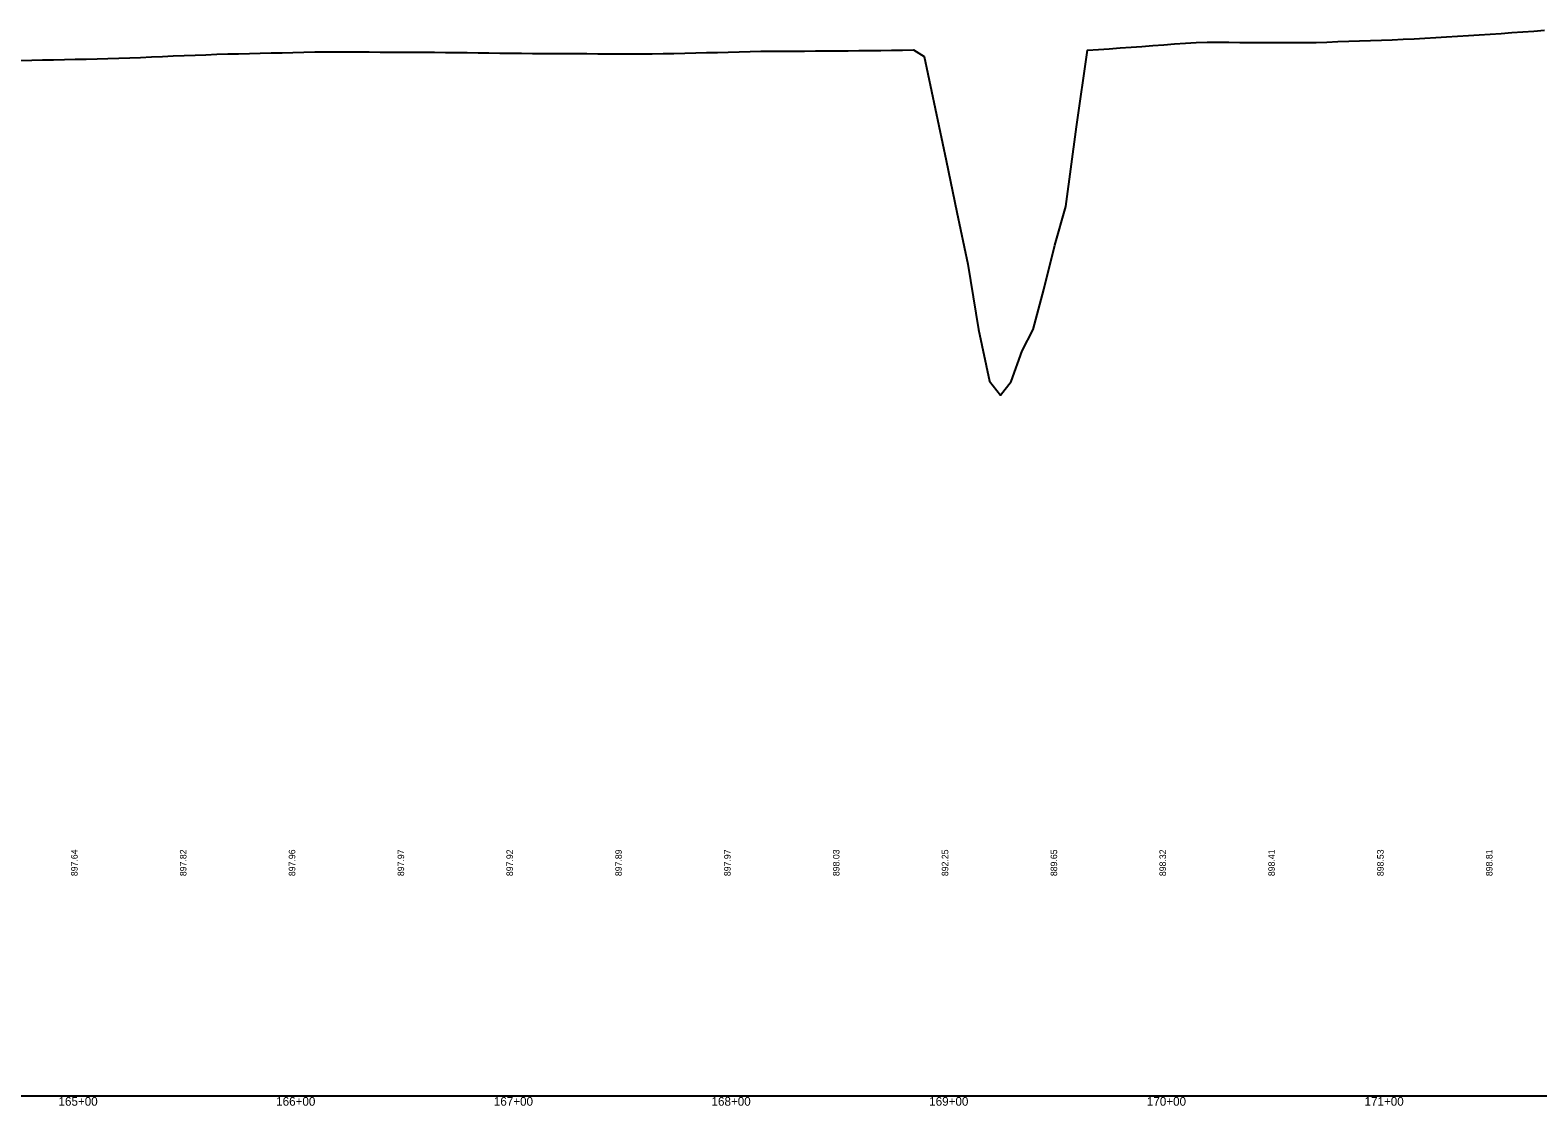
# Model space of a CAD drawing. Extents: x 1475774 to 1484571, y 1098511 to 1113011.
# Drawn here: x 1479549 to 1480241, y 1110507 to 1111001 of the extents above; entities that cross this region are included whole.
import ezdxf

# ---------------------------------------------------------------- set-up
doc = ezdxf.new("R2010")
doc.units = 0
for name, color, linetype in [('RD_DDB_Profile_EX', 7, 'Continuous'), ('RD_DDB_StaTX', 7, 'Continuous'), ('RD_DDB_StripGrade', 7, 'Continuous'), ('RD_GPK_Profile_Cell', 7, 'Continuous')]:
    doc.layers.add(name, color=color, linetype=linetype)

msp = doc.modelspace()

# ---------------------------------------------------------------- linework, layer by layer
at = {"layer": 'RD_DDB_Profile_EX'}
for points in [[(1479964.42, 1110965.08), (1479969.42, 1110941.19), (1479974.42, 1110917.3), (1479979.42, 1110893.42), (1479984.42, 1110863.41), (1479989.42, 1110839.73), (1479994.42, 1110833.29), (1479999.42, 1110839.55), (1480004.42, 1110853.59), (1480009.42, 1110863.52), (1480014.42, 1110881.81), (1480019.42, 1110902.24), (1480024.42, 1110919.92), (1480029.42, 1110956.54), (1480034.42, 1110991.76), (1480039.42, 1110992.13), (1480044.42, 1110992.49), (1480049.42, 1110992.85), (1480054.42, 1110993.21), (1480059.42, 1110993.57), (1480064.42, 1110993.93), (1480069.42, 1110994.29), (1480074.42, 1110994.65), (1480079.42, 1110995.01), (1480084.42, 1110995.37), (1480089.42, 1110995.45), (1480094.42, 1110995.43), (1480099.42, 1110995.42), (1480104.42, 1110995.4), (1480109.42, 1110995.38), (1480114.42, 1110995.37), (1480119.42, 1110995.36), (1480124.42, 1110995.34), (1480129.42, 1110995.32), (1480134.42, 1110995.3), (1480139.42, 1110995.38), (1480144.42, 1110995.56), (1480149.42, 1110995.74), (1480154.42, 1110995.92), (1480159.42, 1110996.1), (1480164.42, 1110996.28), (1480169.42, 1110996.46), (1480174.42, 1110996.63), (1480179.42, 1110996.81), (1480184.42, 1110996.99), (1480189.42, 1110997.26), (1480194.42, 1110997.59), (1480199.42, 1110997.92), (1480204.42, 1110998.25), (1480209.42, 1110998.57), (1480214.42, 1110998.88), (1480219.42, 1110999.21), (1480224.42, 1110999.54), (1480229.42, 1110999.86), (1480234.42, 1111000.19), (1480239.42, 1111000.59), (1480244.42, 1111001.02)], [(1479544.42, 1110987.1), (1479549.42, 1110987.21), (1479554.42, 1110987.32), (1479559.42, 1110987.43), (1479564.42, 1110987.53), (1479569.42, 1110987.63), (1479574.42, 1110987.73), (1479579.42, 1110987.82), (1479584.42, 1110987.91), (1479589.42, 1110988.08), (1479594.42, 1110988.3), (1479599.42, 1110988.52), (1479604.42, 1110988.74), (1479609.42, 1110988.94), (1479614.42, 1110989.14), (1479619.42, 1110989.34), (1479624.42, 1110989.54), (1479629.42, 1110989.73), (1479634.42, 1110989.93), (1479639.42, 1110990.07), (1479644.42, 1110990.19), (1479649.42, 1110990.3), (1479654.42, 1110990.42), (1479659.42, 1110990.53), (1479664.42, 1110990.66), (1479669.42, 1110990.77), (1479674.42, 1110990.89), (1479679.42, 1110991), (1479684.42, 1110991.11), (1479689.42, 1110991.08), (1479694.42, 1110991.05), (1479699.42, 1110991.02), (1479704.42, 1110990.99), (1479709.42, 1110990.97), (1479714.42, 1110990.94), (1479719.42, 1110990.91), (1479724.42, 1110990.89), (1479729.42, 1110990.86), (1479734.42, 1110990.84), (1479739.42, 1110990.79), (1479744.42, 1110990.73), (1479749.42, 1110990.68), (1479754.42, 1110990.62), (1479759.42, 1110990.56), (1479764.42, 1110990.51), (1479769.42, 1110990.45), (1479774.42, 1110990.4), (1479779.42, 1110990.34), (1479784.42, 1110990.29), (1479789.42, 1110990.28), (1479794.42, 1110990.25), (1479799.42, 1110990.23), (1479804.42, 1110990.21), (1479809.42, 1110990.18), (1479814.42, 1110990.16), (1479819.42, 1110990.13), (1479824.42, 1110990.11), (1479829.42, 1110990.09), (1479834.42, 1110990.1), (1479839.42, 1110990.22), (1479844.42, 1110990.34), (1479849.42, 1110990.47), (1479854.42, 1110990.59), (1479859.42, 1110990.68), (1479864.42, 1110990.81), (1479869.42, 1110990.93), (1479874.42, 1110991.05), (1479879.42, 1110991.18), (1479884.42, 1110991.28), (1479889.42, 1110991.32), (1479894.42, 1110991.35), (1479899.42, 1110991.39), (1479904.42, 1110991.43), (1479909.42, 1110991.47), (1479914.42, 1110991.51), (1479919.42, 1110991.55), (1479924.42, 1110991.58), (1479929.42, 1110991.62), (1479934.42, 1110991.66), (1479939.42, 1110991.73), (1479944.42, 1110991.8), (1479949.42, 1110991.87), (1479954.42, 1110991.94), (1479959.42, 1110988.97), (1479964.42, 1110965.08)]]:
    msp.add_lwpolyline(points, dxfattribs=at)
at = {"layer": 'RD_GPK_Profile_Cell'}
msp.add_line((1477570.98, 1110511.25), (1484570.98, 1110511.25), dxfattribs=at)

# ---------------------------------------------------------------- texts
at = {"layer": 'RD_DDB_StaTX'}
for s, p in [('165+00', (1479561.7, 1110506.75)), ('166+00', (1479661.7, 1110506.75)), ('167+00', (1479761.7, 1110506.75)), ('168+00', (1479861.7, 1110506.75)), ('169+00', (1479961.7, 1110506.75)), ('170+00', (1480061.7, 1110506.75)), ('171+00', (1480161.7, 1110506.75))]:
    msp.add_text(s, height=4, dxfattribs=at).set_placement(p)
at = {"layer": 'RD_DDB_StripGrade'}
for s, p in [('897.64', (1479570.48, 1110612.25)), ('897.82', (1479620.48, 1110612.25)), ('897.96', (1479670.48, 1110612.25)), ('897.97', (1479720.48, 1110612.25)), ('897.92', (1479770.48, 1110612.25)), ('897.89', (1479820.48, 1110612.25)), ('897.97', (1479870.48, 1110612.25)), ('898.03', (1479920.48, 1110612.25)), ('892.25', (1479970.48, 1110612.25)), ('889.65', (1480020.48, 1110612.25)), ('898.32', (1480070.48, 1110612.25)), ('898.41', (1480120.48, 1110612.25)), ('898.53', (1480170.48, 1110612.25)), ('898.81', (1480220.48, 1110612.25))]:
    msp.add_text(s, height=3, rotation=90, dxfattribs=at).set_placement(p)

doc.saveas('drawing.dxf')
